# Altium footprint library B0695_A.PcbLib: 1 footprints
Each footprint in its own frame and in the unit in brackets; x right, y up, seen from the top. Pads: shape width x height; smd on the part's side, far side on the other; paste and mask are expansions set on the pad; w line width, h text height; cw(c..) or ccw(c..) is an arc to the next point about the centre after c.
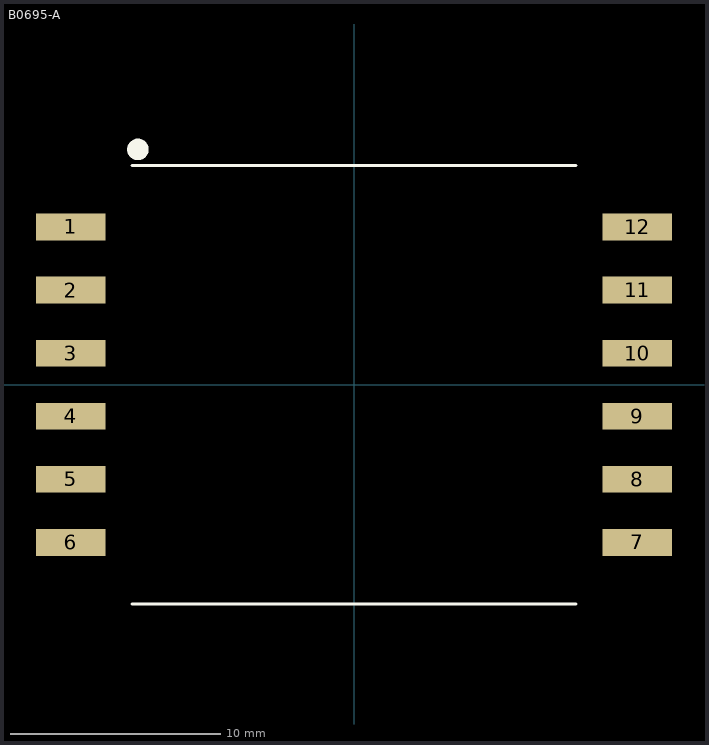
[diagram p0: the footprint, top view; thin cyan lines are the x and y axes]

## B0695-A [mil] "1:0.23 and 1:0.69 Transformer"
height 450
pads (12):
  rect 130x50 smd: 1(-530,295) 2(-530,177) 3(-530,59) 4(-530,-59) 5(-530,-177) 6(-530,-295) 7(530,-295) 8(530,-177) 9(530,-59) 10(530,59) 11(530,177) 12(530,295)
Top Overlay:
  circle w20: c-404.14,440 r10
  lines w5: -415,-410 415,-410 ; -415,410 415,410
M5 Assembly Top:
  text ".Designator" at -60,-20 h40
